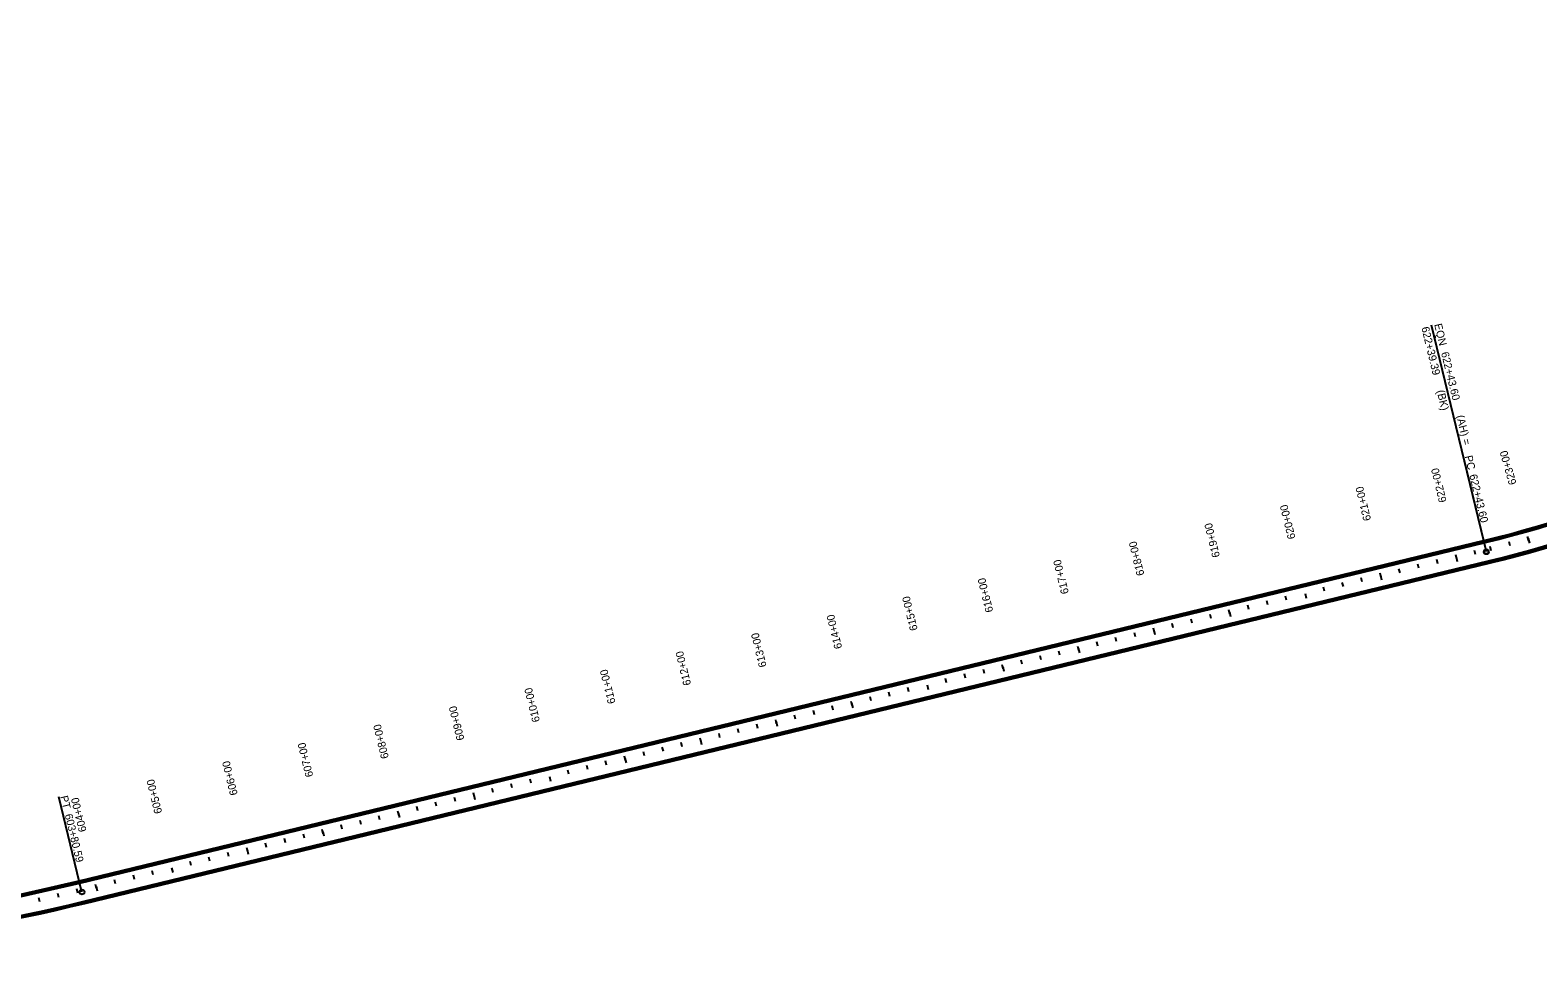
# Model space of a CAD drawing. Extents: x 22755720 to 22802976, y 6232173 to 6285384.
# Drawn here: x 22795110 to 22797050, y 6281907 to 6283110 of the extents above; entities that cross this region are included whole.
import ezdxf

# ---------------------------------------------------------------- set-up
doc = ezdxf.new("R2010")
doc.units = 0
for name, color, linetype in [('Culvert', 7, 'Continuous'), ('Draft_3', 7, 'Continuous'), ('dsnCellElements', 7, 'Continuous'), ('dsnTextNote', 7, 'Continuous'), ('TextNonPlot', 7, 'Continuous')]:
    doc.layers.add(name, color=color, linetype=linetype)

msp = doc.modelspace()

# ---------------------------------------------------------------- linework, layer by layer
at = {"layer": 'Culvert'}
for p, q in [((22797013.8, 6282447.2), (22797012.4, 6282452.5)), ((22797037, 6282456.7), (22797038.7, 6282450.9)), ((22796944.3, 6282433.2), (22796945.8, 6282427.2)), ((22796969.4, 6282436.1), (22796968.1, 6282441.4)), ((22796989.6, 6282441), (22796988.3, 6282446.3)), ((22796872.2, 6282412.5), (22796870.9, 6282417.8)), ((22796896.5, 6282418.4), (22796895.2, 6282423.7)), ((22796920.8, 6282424.3), (22796919.5, 6282429.6)), ((22796775, 6282389), (22796773.7, 6282394.3)), ((22796799.3, 6282394.9), (22796798, 6282400.2)), ((22796823.6, 6282400.8), (22796822.3, 6282406.1)), ((22796847.1, 6282409.6), (22796848.6, 6282403.7)), ((22796702.1, 6282371.3), (22796700.8, 6282376.6)), ((22796726.4, 6282377.2), (22796725.1, 6282382.5)), ((22796750, 6282386.1), (22796751.4, 6282380.1)), ((22796629.2, 6282353.7), (22796627.9, 6282359)), ((22796652.8, 6282362.5), (22796654.2, 6282356.6)), ((22796677.8, 6282365.5), (22796676.5, 6282370.8)), ((22796532, 6282330.2), (22796530.7, 6282335.5)), ((22796555.6, 6282339), (22796557, 6282333.1)), ((22796580.6, 6282341.9), (22796579.3, 6282347.2)), ((22796604.9, 6282347.8), (22796603.6, 6282353.1)), ((22796458.4, 6282315.5), (22796459.8, 6282309.5)), ((22796483.4, 6282318.4), (22796482.1, 6282323.7)), ((22796507.7, 6282324.3), (22796506.4, 6282329.6)), ((22796386.2, 6282294.9), (22796384.9, 6282300.2)), ((22796410.5, 6282300.7), (22796409.2, 6282306)), ((22796434.8, 6282306.6), (22796433.5, 6282311.9)), ((22796289, 6282271.3), (22796287.7, 6282276.6)), ((22796313.3, 6282277.2), (22796312, 6282282.5)), ((22796337.6, 6282283.1), (22796336.3, 6282288.4)), ((22796361.2, 6282291.9), (22796362.6, 6282286)), ((22796216.1, 6282253.7), (22796214.8, 6282259)), ((22796240.4, 6282259.5), (22796239.1, 6282264.9)), ((22796264, 6282268.4), (22796265.4, 6282262.5)), ((22796143.2, 6282236), (22796141.9, 6282241.3)), ((22796166.8, 6282244.9), (22796168.2, 6282238.9)), ((22796191.8, 6282247.8), (22796190.5, 6282253.1)), ((22796046, 6282212.5), (22796044.8, 6282217.8)), ((22796069.6, 6282221.3), (22796071.1, 6282215.4)), ((22796094.6, 6282224.2), (22796093.4, 6282229.5)), ((22796118.9, 6282230.1), (22796117.6, 6282235.4)), ((22795997.4, 6282200.7), (22795996.2, 6282206)), ((22796021.7, 6282206.6), (22796020.5, 6282211.9)), ((22795900.3, 6282177.2), (22795899, 6282182.5)), ((22795924.6, 6282183.1), (22795923.3, 6282188.4)), ((22795948.8, 6282188.9), (22795947.6, 6282194.2)), ((22795972.4, 6282197.8), (22795973.9, 6282191.8)), ((22795827.4, 6282159.5), (22795826.1, 6282164.8)), ((22795851.7, 6282165.4), (22795850.4, 6282170.7)), ((22795875.2, 6282174.3), (22795876.7, 6282168.3)), ((22795730.2, 6282136), (22795728.9, 6282141.3)), ((22795754.5, 6282141.9), (22795753.2, 6282147.2)), ((22795778, 6282150.7), (22795779.5, 6282144.8)), ((22795803.1, 6282153.6), (22795801.8, 6282158.9)), ((22795657.3, 6282118.3), (22795656, 6282123.6)), ((22795680.9, 6282127.2), (22795682.3, 6282121.2)), ((22795705.9, 6282130.1), (22795704.6, 6282135.4)), ((22795583.7, 6282103.7), (22795585.1, 6282097.7)), ((22795608.7, 6282106.6), (22795607.4, 6282111.9)), ((22795633, 6282112.4), (22795631.7, 6282117.8)), ((22795511.5, 6282083), (22795510.2, 6282088.3)), ((22795535.8, 6282088.9), (22795534.5, 6282094.2)), ((22795560.1, 6282094.8), (22795558.8, 6282100.1)), ((22795414.3, 6282059.5), (22795413, 6282064.8)), ((22795438.6, 6282065.4), (22795437.3, 6282070.7)), ((22795462.9, 6282071.3), (22795461.6, 6282076.6)), ((22795486.5, 6282080.1), (22795487.9, 6282074.2)), ((22795341.4, 6282041.8), (22795340.1, 6282047.1)), ((22795365.7, 6282047.7), (22795364.4, 6282053)), ((22795389.3, 6282056.6), (22795390.7, 6282050.6)), ((22795244.2, 6282018.3), (22795242.9, 6282023.6)), ((22795268.5, 6282024.2), (22795267.2, 6282029.5)), ((22795292.1, 6282033), (22795293.5, 6282027.1)), ((22795317.1, 6282036), (22795315.8, 6282041.3)), ((22795171.3, 6282000.7), (22795170, 6282006)), ((22795194.9, 6282009.5), (22795196.3, 6282003.6)), ((22795219.9, 6282012.4), (22795218.6, 6282017.7)), ((22795122.6, 6281989.4), (22795121.4, 6281994.7)), ((22795147, 6281994.9), (22795145.8, 6282000.2))]:
    msp.add_line(p, q, dxfattribs=at)
at = {"layer": 'Draft_3'}
for p, q in [((22796983.3, 6282439.5), (22796912.7, 6282731)), ((22796983.3, 6282439.5), (22796953.7, 6282561.9)), ((22796953.7, 6282561.9), (22796953.7, 6282561.9)), ((22795176.8, 6282002), (22795147.1, 6282124.4)), ((22795147.1, 6282124.4), (22795147.1, 6282124.4))]:
    msp.add_line(p, q, dxfattribs=at)
for centre, radius in [((22796983.3, 6282439.5), 3.12), ((22796983.3, 6282439.5), 2.67), ((22795176.8, 6282002), 3.12)]:
    msp.add_circle(centre, radius, dxfattribs=at)
at = {"layer": 'dsnCellElements'}
for p, q in [((22795173.2, 6282016.5), (22796979.8, 6282454)), ((22795173.5, 6282015.6), (22796980, 6282453.1)), ((22795180.1, 6281988.4), (22796986.6, 6282425.8)), ((22795180.3, 6281987.4), (22796986.9, 6282424.9))]:
    msp.add_line(p, q, dxfattribs=at)
for centre, radius, start, end in [((22796646.2, 6283831.7), 1417.5, 283.6129, 329.4129), ((22796646.2, 6283831.7), 1418.5, 283.6129, 329.4129), ((22796646.2, 6283831.7), 1446.5, 283.6129, 329.4129), ((22796646.2, 6283831.7), 1447.5, 283.6129, 329.4129), ((22794502.4, 6284786.5), 2850, 271.2295, 283.6129), ((22794502.4, 6284786.5), 2851, 271.2295, 283.6129), ((22794502.4, 6284786.5), 2879, 271.2295, 283.6129), ((22794502.4, 6284786.5), 2880, 271.2295, 283.6129)]:
    msp.add_arc(centre, radius, start, end, dxfattribs=at)
at = {"layer": 'dsnTextNote'}
for p, q in [((22797037.9, 6282453.8), (22797036.4, 6282459.1)), ((22796945.1, 6282430.2), (22796943.8, 6282435.5)), ((22796847.9, 6282406.6), (22796846.6, 6282412)), ((22796750, 6282386.1), (22796751.4, 6282380.1)), ((22796653.5, 6282359.6), (22796652.2, 6282364.9)), ((22796556.3, 6282336), (22796555, 6282341.3)), ((22796459.1, 6282312.5), (22796457.8, 6282317.8)), ((22796361.9, 6282289), (22796360.6, 6282294.3)), ((22796264, 6282268.4), (22796265.4, 6282262.5)), ((22796167.5, 6282241.9), (22796166.2, 6282247.2)), ((22796070.3, 6282218.4), (22796069.1, 6282223.7)), ((22795973.1, 6282194.8), (22795971.9, 6282200.1)), ((22795876, 6282171.3), (22795874.7, 6282176.6)), ((22795778, 6282150.7), (22795779.5, 6282144.8)), ((22795681.6, 6282124.2), (22795680.3, 6282129.5)), ((22795584.4, 6282100.7), (22795583.1, 6282106)), ((22795487.2, 6282077.1), (22795485.9, 6282082.4)), ((22795390, 6282053.6), (22795388.7, 6282058.9)), ((22795292.1, 6282033), (22795293.5, 6282027.1)), ((22795195.6, 6282006.5), (22795194.3, 6282011.8))]:
    msp.add_line(p, q, dxfattribs=at)
at = {"layer": 'TextNonPlot'}
for p, q in [((22795173.9, 6282013.6), (22796980.5, 6282451.1)), ((22795173.9, 6282013.6), (22796980.5, 6282451.1)), ((22795179.6, 6281990.3), (22796986.2, 6282427.8))]:
    msp.add_line(p, q, dxfattribs=at)
for centre, radius, start, end in [((22796646.2, 6283831.7), 1420.5, 283.6129, 329.4129), ((22796646.2, 6283831.7), 1420.5, 283.6129, 329.4129), ((22796646.2, 6283831.7), 1444.5, 283.6129, 329.4129), ((22794502.4, 6284786.5), 2853, 271.2295, 283.6129), ((22794502.4, 6284786.5), 2853, 271.2295, 283.6129), ((22794502.4, 6284786.5), 2877, 271.2295, 283.6129)]:
    msp.add_arc(centre, radius, start, end, dxfattribs=at)

# ---------------------------------------------------------------- texts
at = {"layer": 'Culvert'}
for s, rotation, p in [('623+00', 105.8687, (22797022.2, 6282527.3)), ('622+00', 103.6129, (22796932.3, 6282504.3)), ('621+00', 103.6129, (22796835.1, 6282480.7)), ('620+00', 103.6129, (22796737.9, 6282457.2)), ('619+00', 103.6129, (22796640.7, 6282433.6)), ('618+00', 103.6129, (22796543.5, 6282410.1)), ('617+00', 103.6129, (22796446.3, 6282386.6)), ('616+00', 103.6129, (22796349.1, 6282363)), ('615+00', 103.6129, (22796251.9, 6282339.5)), ('614+00', 103.6129, (22796154.7, 6282316)), ('613+00', 103.6129, (22796057.6, 6282292.4)), ('612+00', 103.6129, (22795960.4, 6282268.9)), ('611+00', 103.6129, (22795863.2, 6282245.4)), ('610+00', 103.6129, (22795766, 6282221.8)), ('609+00', 103.6129, (22795668.8, 6282198.3)), ('608+00', 103.6129, (22795571.6, 6282174.8)), ('607+00', 103.6129, (22795474.4, 6282151.2)), ('606+00', 103.6129, (22795377.2, 6282127.7)), ('605+00', 103.6129, (22795280, 6282104.1)), ('604+00', 103.6129, (22795182.8, 6282080.6))]:
    msp.add_text(s, height=10.02, rotation=rotation, dxfattribs=at).set_placement(p)
at = {"layer": 'Draft_3'}
for s, p in [('622+39.39', (22796899.6, 6282727.8)), ('EQN ', (22796916.1, 6282731.9)), ('622+43.60', (22796924.9, 6282695.5)), ('(BK)', (22796919.3, 6282646.5)), ('(AH) = ', (22796944.6, 6282614.2)), ('PC', (22796955.3, 6282562.3)), ('622+43.60', (22796961.2, 6282538.1)), ('PT', (22795148.7, 6282124.8)), ('603+80.59', (22795154.5, 6282101.3))]:
    msp.add_text(s, height=10.02, rotation=283.6129, dxfattribs=at).set_placement(p)
at = {"layer": 'dsnTextNote'}
for s, p in [('620+00', (22796737.9, 6282457.2)), ('615+00', (22796251.9, 6282339.5)), ('610+00', (22795766, 6282221.8)), ('605+00', (22795280, 6282104.1))]:
    msp.add_text(s, height=10.02, rotation=103.6129, dxfattribs=at).set_placement(p)

doc.saveas('drawing.dxf')
